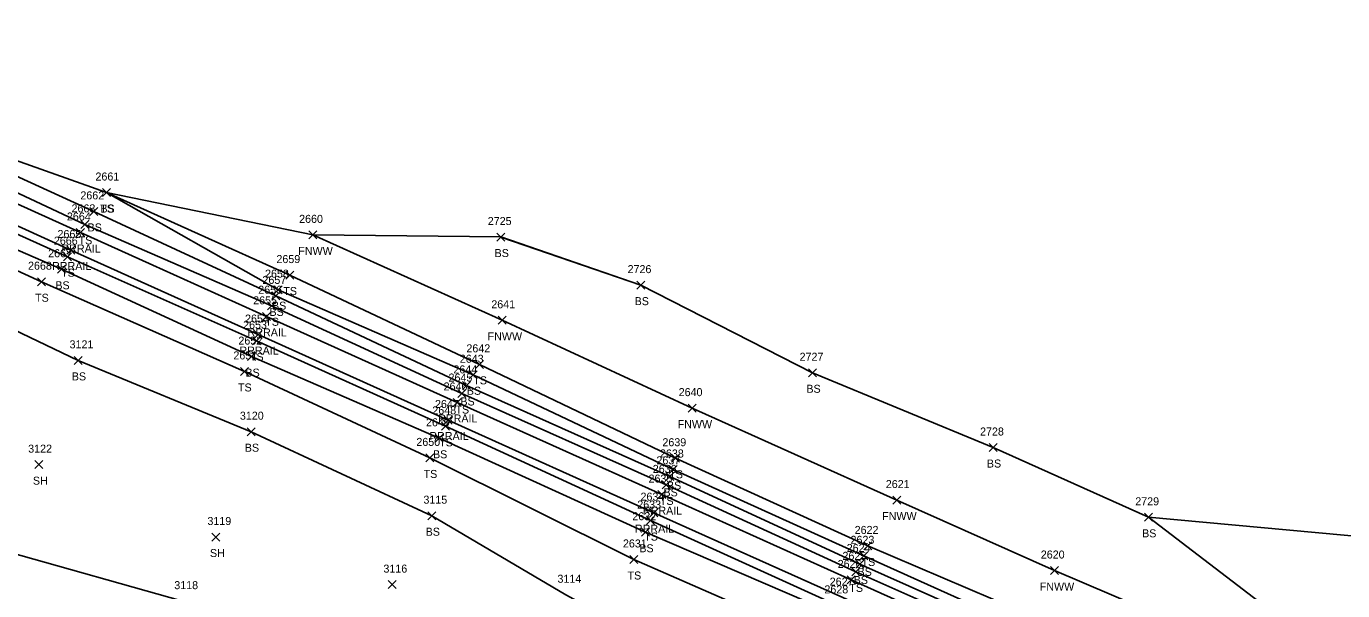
# Model space of a CAD drawing. Extents: x 1599569 to 1610055, y 642560 to 647860.
# Drawn here: x 1600804.5 to 1601133.3, y 647397.5 to 647538.4 of the extents above; entities that cross this region are included whole.
import ezdxf

# ---------------------------------------------------------------- set-up
doc = ezdxf.new("R2010")
doc.units = 0
for name, color, linetype in [('L_A', 7, 'Continuous'), ('L_I', 7, 'Continuous'), ('L_TIC', 7, 'Continuous'), ('LABL', 7, 'Continuous'), ('LELB', 7, 'Continuous'), ('LFNC', 7, 'Continuous'), ('LSOGP', 7, 'Continuous'), ('R_A', 7, 'Continuous'), ('R_I', 7, 'Continuous'), ('R_TIC', 7, 'Continuous'), ('RR', 7, 'Continuous')]:
    doc.layers.add(name, color=color, linetype=linetype)

msp = doc.modelspace()

# ---------------------------------------------------------------- linework, layer by layer
at = {"layer": 'L_TIC'}
for points in [[(1600823.54, 647495.94), (1600825.54, 647497.94)], [(1600825.54, 647495.94), (1600823.54, 647497.94)], [(1600823.54, 647495.94), (1600825.54, 647497.94)], [(1600825.54, 647495.94), (1600823.54, 647497.94)], [(1600820.34, 647491.23), (1600822.34, 647493.23)], [(1600822.34, 647491.23), (1600820.34, 647493.23)], [(1600818.14, 647487.99), (1600820.14, 647489.99)], [(1600820.14, 647487.99), (1600818.14, 647489.99)], [(1600875.08, 647485.37), (1600877.08, 647487.37)], [(1600877.08, 647485.37), (1600875.08, 647487.37)], [(1600922.02, 647484.83), (1600924.02, 647486.83)], [(1600924.02, 647484.83), (1600922.02, 647486.83)], [(1600813.78, 647479.92), (1600815.78, 647481.92)], [(1600815.78, 647479.92), (1600813.78, 647481.92)], [(1600812.3, 647476.78), (1600814.3, 647478.78)], [(1600814.3, 647476.78), (1600812.3, 647478.78)], [(1600869.28, 647475.33), (1600871.28, 647477.33)], [(1600871.28, 647475.33), (1600869.28, 647477.33)], [(1600807.26, 647473.67), (1600809.26, 647475.67)], [(1600809.26, 647473.67), (1600807.26, 647475.67)], [(1600866.43, 647471.68), (1600868.43, 647473.68)], [(1600868.43, 647471.68), (1600866.43, 647473.68)], [(1600957.02, 647472.82), (1600959.02, 647474.82)], [(1600959.02, 647472.82), (1600957.02, 647474.82)], [(1600864.78, 647467.67), (1600866.78, 647469.67)], [(1600866.78, 647467.67), (1600864.78, 647469.67)], [(1600865.79, 647470.13), (1600867.79, 647472.13)], [(1600867.79, 647470.13), (1600865.79, 647472.13)], [(1600922.39, 647464.04), (1600924.39, 647466.04)], [(1600924.39, 647464.04), (1600922.39, 647466.04)], [(1600860.95, 647458.92), (1600862.95, 647460.92)], [(1600862.95, 647458.92), (1600860.95, 647460.92)], [(1600859.78, 647454.97), (1600861.78, 647456.97)], [(1600861.78, 647454.97), (1600859.78, 647456.97)], [(1600816.41, 647454.03), (1600818.41, 647456.03)], [(1600818.41, 647454.03), (1600816.41, 647456.03)], [(1600857.96, 647451.27), (1600859.96, 647453.27)], [(1600859.96, 647451.27), (1600857.96, 647453.27)], [(1600916.74, 647453.04), (1600918.74, 647455.04)], [(1600918.74, 647453.04), (1600916.74, 647455.04)], [(1600999.93, 647450.94), (1601001.93, 647452.94)], [(1601001.93, 647450.94), (1600999.93, 647452.94)], [(1600913.49, 647447.77), (1600915.49, 647449.77)], [(1600915.49, 647447.77), (1600913.49, 647449.77)], [(1600915.08, 647450.44), (1600917.08, 647452.44)], [(1600917.08, 647450.44), (1600915.08, 647452.44)], [(1600912.28, 647445.74), (1600914.28, 647447.74)], [(1600914.28, 647445.74), (1600912.28, 647447.74)], [(1600969.86, 647442.1), (1600971.86, 647444.1)], [(1600971.86, 647442.1), (1600969.86, 647444.1)], [(1600859.62, 647436.22), (1600861.62, 647438.22)], [(1600861.62, 647436.22), (1600859.62, 647438.22)], [(1600906.65, 647434.58), (1600908.65, 647436.58)], [(1600908.65, 647434.58), (1600906.65, 647436.58)], [(1600908.23, 647437.57), (1600910.23, 647439.57)], [(1600910.23, 647437.57), (1600908.23, 647439.57)], [(1601045.02, 647432.27), (1601047.02, 647434.27)], [(1601047.02, 647432.27), (1601045.02, 647434.27)], [(1600806.64, 647427.99), (1600808.64, 647429.99)], [(1600808.64, 647427.99), (1600806.64, 647429.99)], [(1600904.33, 647429.67), (1600906.33, 647431.67)], [(1600906.33, 647429.67), (1600904.33, 647431.67)], [(1600965.71, 647429.59), (1600967.71, 647431.59)], [(1600967.71, 647429.59), (1600965.71, 647431.59)], [(1600964.22, 647425.07), (1600966.22, 647427.07)], [(1600966.22, 647425.07), (1600964.22, 647427.07)], [(1600965.1, 647426.78), (1600967.1, 647428.78)], [(1600967.1, 647426.78), (1600965.1, 647428.78)], [(1600963.35, 647422.93), (1600965.35, 647424.93)], [(1600965.35, 647422.93), (1600963.35, 647424.93)], [(1601020.95, 647419.15), (1601022.95, 647421.15)], [(1601022.95, 647419.15), (1601020.95, 647421.15)], [(1600904.82, 647415.24), (1600906.82, 647417.24)], [(1600906.82, 647415.24), (1600904.82, 647417.24)], [(1601083.8, 647414.84), (1601085.8, 647416.84)], [(1601085.8, 647414.84), (1601083.8, 647416.84)], [(1600959.43, 647414.03), (1600961.43, 647416.03)], [(1600961.43, 647414.03), (1600959.43, 647416.03)], [(1600850.87, 647409.92), (1600852.87, 647411.92)], [(1600852.87, 647409.92), (1600850.87, 647411.92)], [(1600958.19, 647411.11), (1600960.19, 647413.11)], [(1600960.19, 647411.11), (1600958.19, 647413.11)], [(1601012.7, 647405.22), (1601014.7, 647407.22)], [(1601014.7, 647405.22), (1601012.7, 647407.22)], [(1601013.73, 647407.69), (1601015.73, 647409.69)], [(1601015.73, 647407.69), (1601013.73, 647409.69)], [(1600955.28, 647404.31), (1600957.28, 647406.31)], [(1600957.28, 647404.31), (1600955.28, 647406.31)], [(1601011.74, 647403.18), (1601013.74, 647405.18)], [(1601013.74, 647403.18), (1601011.74, 647405.18)], [(1601060.33, 647401.55), (1601062.33, 647403.55)], [(1601062.33, 647401.55), (1601060.33, 647403.55)], [(1601010.7, 647401.22), (1601012.7, 647403.22)], [(1601012.7, 647401.22), (1601010.7, 647403.22)], [(1600894.88, 647398.03), (1600896.88, 647400.03)], [(1600896.88, 647398.03), (1600894.88, 647400.03)]]:
    msp.add_lwpolyline(points, dxfattribs=at)
at = {"layer": 'LABL'}
msp.add_lwpolyline([(1600549.16, 647482.12), (1600587.34, 647468), (1600622.01, 647455.54), (1600659.72, 647441.77), (1600697.35, 647428.92), (1600725.07, 647418.09), (1600758.35, 647406.43), (1600789.53, 647394.65), (1600829.98, 647379.88), (1600858.93, 647365.17), (1600893.05, 647356.35), (1600928.59, 647369.58), (1600886.67, 647382.78), (1600843.57, 647394.9), (1600799.84, 647407.24), (1600758.94, 647419.51), (1600717.33, 647433.23), (1600675.44, 647448.96), (1600633.1, 647463.38), (1600594.68, 647476.25), (1600537.7, 647496.6)], dxfattribs=at)
at = {"layer": 'LELB'}
for points in [[(1601042.57, 647341.43), (1601046.92, 647357.23), (1601002.18, 647385.23), (1600956.28, 647405.31), (1600905.33, 647430.67), (1600858.96, 647452.27), (1600808.26, 647474.67), (1600756.41, 647498.48), (1600709.6, 647519.51), (1600666.09, 647538.44)], [(1601329.86, 647260.18), (1601292.61, 647278.06), (1601262.72, 647292.4), (1601226.59, 647308.21), (1601190.68, 647323.36), (1601158.75, 647338.43), (1601129.91, 647351.62), (1601096.68, 647366.43), (1601056.58, 647384.54), (1601012.74, 647404.18), (1600965.22, 647426.07), (1600914.49, 647448.77), (1600866.79, 647471.13), (1600821.34, 647492.23), (1600763.72, 647518.52)], [(1601329.08, 647258.95), (1601292.39, 647275.61), (1601261.46, 647289.71), (1601225.27, 647305.87), (1601190.14, 647321.67), (1601157.62, 647336.35), (1601128.98, 647349.36), (1601095.53, 647364.39), (1601055.96, 647382.57), (1601011.7, 647402.22), (1600964.35, 647423.93), (1600913.28, 647446.74), (1600865.78, 647468.67), (1600819.14, 647488.99), (1600762.95, 647515.26)], [(1601006.37, 647351.71), (1601004.39, 647364.75), (1600971.27, 647379.2), (1600939.3, 647396.5), (1600905.82, 647416.24), (1600860.62, 647437.22), (1600817.41, 647455.03), (1600778.97, 647473.37), (1600739.63, 647487.55), (1600693.85, 647507.84)], [(1601326.17, 647250.65), (1601291.06, 647266.1), (1601257.88, 647281.25), (1601220.45, 647296.99), (1601187.26, 647312.94), (1601153.32, 647328.3), (1601124.87, 647340.95), (1601091.41, 647355.79), (1601053.43, 647373.03), (1601007.18, 647393.84), (1600960.43, 647415.03), (1600909.23, 647438.57), (1600861.95, 647459.92), (1600814.78, 647480.92), (1600758.97, 647506.06)], [(1601324.87, 647247.72), (1601290.33, 647262.4), (1601257.07, 647278.05), (1601219.4, 647295.14), (1601185.88, 647311.18), (1601152.37, 647326.07), (1601123.71, 647338.45), (1601090.36, 647353.63), (1601052.5, 647371.13), (1601006, 647391.96), (1600959.19, 647412.11), (1600907.65, 647435.58), (1600860.78, 647455.97), (1600813.3, 647477.78), (1600757.71, 647501.96)], [(1601277.64, 647306.94), (1601247.91, 647313.96), (1601233.47, 647321.04), (1601196.65, 647335.07), (1601162.36, 647345.97), (1601131.17, 647354.49), (1601097.9, 647368.75), (1601057.17, 647386.63), (1601013.7, 647406.22), (1600966.1, 647427.78), (1600916.08, 647451.44), (1600867.43, 647472.68), (1600824.54, 647496.94)], [(1601163.89, 647358.89), (1601162.92, 647352.78), (1601136.88, 647363.46), (1601101.2, 647375.84), (1601058.43, 647390.08), (1601014.73, 647408.69), (1600966.71, 647430.59), (1600917.74, 647454.04), (1600870.28, 647476.33), (1600824.54, 647496.94)], [(1600923.02, 647485.83), (1600958.02, 647473.82), (1601000.93, 647451.94), (1601046.02, 647433.27), (1601084.8, 647415.84), (1601116.74, 647391.45), (1601157.19, 647373.2)]]:
    msp.add_lwpolyline(points, dxfattribs=at)
at = {"layer": 'LFNC'}
msp.add_lwpolyline([(1601438.38, 647230.38), (1601406.08, 647246.23), (1601390.36, 647253.65), (1601325.07, 647284.52), (1601295.93, 647298.24), (1601277.64, 647306.94), (1601251.54, 647319.32), (1601236.24, 647326.06), (1601200.38, 647343.03), (1601163.89, 647358.89), (1601138.18, 647369.81), (1601105.25, 647383.87), (1601061.33, 647402.55), (1601021.95, 647420.15), (1600970.86, 647443.1), (1600923.39, 647465.04), (1600876.08, 647486.37)], dxfattribs=at)
at = {"layer": 'LSOGP'}
msp.add_lwpolyline([(1601329.63, 647421.95), (1601289.24, 647420.17), (1601272.46, 647419.67), (1601258.21, 647415.18), (1601255.18, 647413.85), (1601254.97, 647413.31), (1601235.02, 647405.14), (1601227.44, 647408.51), (1601219.86, 647411.89), (1601212.28, 647415.27), (1601190.18, 647411.64), (1601176.24, 647407.45), (1601084.8, 647415.84), (1601084.8, 647415.85), (1601046.02, 647433.27), (1601000.93, 647451.95), (1600958.02, 647473.82), (1600923.02, 647485.84), (1600876.08, 647486.37), (1600824.54, 647496.94), (1600763.73, 647518.52)], dxfattribs=at)
at = {"layer": 'R_TIC'}
for points in [[(1600816.98, 647485.96), (1600818.98, 647487.96)], [(1600818.98, 647485.96), (1600816.98, 647487.96)], [(1600814.63, 647481.59), (1600816.63, 647483.59)], [(1600816.63, 647481.59), (1600814.63, 647483.59)], [(1600863.46, 647465.02), (1600865.46, 647467.02)], [(1600865.46, 647465.02), (1600863.46, 647467.02)], [(1600861.44, 647460.47), (1600863.44, 647462.47)], [(1600863.44, 647460.47), (1600861.44, 647462.47)], [(1600911.09, 647443.53), (1600913.09, 647445.53)], [(1600913.09, 647443.53), (1600911.09, 647445.53)], [(1600908.88, 647439.14), (1600910.88, 647441.14)], [(1600910.88, 647439.14), (1600908.88, 647441.14)], [(1600962.24, 647420.51), (1600964.24, 647422.51)], [(1600964.24, 647420.51), (1600962.24, 647422.51)], [(1600960.24, 647416), (1600962.24, 647418)], [(1600962.24, 647416), (1600960.24, 647418)], [(1601009.55, 647399.2), (1601011.55, 647401.2)], [(1601011.55, 647399.2), (1601009.55, 647401.2)]]:
    msp.add_lwpolyline(points, dxfattribs=at)
at = {"layer": 'RR'}
for points in [[(1601328.26, 647256.93), (1601292.48, 647273.14), (1601260.65, 647287.58), (1601223.96, 647303.96), (1601189.34, 647319.67), (1601156.57, 647334.47), (1601128.05, 647347.29), (1601094.57, 647362.49), (1601054.86, 647380.37), (1601010.55, 647400.2), (1600963.24, 647421.51), (1600912.09, 647444.53), (1600864.46, 647466.02), (1600817.98, 647486.96), (1600761.67, 647512.45)], [(1601326.5, 647252.29), (1601291.28, 647268.22), (1601258.56, 647283.04), (1601221.6, 647299.6), (1601187.65, 647314.96), (1601154.54, 647329.95), (1601125.78, 647342.91), (1601092.45, 647357.88), (1601054.06, 647375.24), (1601008.5, 647395.78), (1600961.24, 647417), (1600909.88, 647440.14), (1600862.44, 647461.47), (1600815.63, 647482.59), (1600759.94, 647507.87)]]:
    msp.add_lwpolyline(points, dxfattribs=at)

# ---------------------------------------------------------------- texts
at = {"layer": 'L_A'}
for s, p in [('TS', (1600822.95, 647491.94)), ('BS', (1600822.99, 647491.94)), ('BS', (1600819.78, 647487.23)), ('TS', (1600817.54, 647483.99)), ('FNWW', (1600872.43, 647481.37)), ('BS', (1600921.47, 647480.83)), ('TS', (1600813.19, 647475.92)), ('BS', (1600811.74, 647472.78)), ('TS', (1600868.69, 647471.33)), ('TS', (1600806.67, 647469.67)), ('BS', (1600865.87, 647467.68)), ('BS', (1600956.46, 647468.82)), ('BS', (1600865.23, 647466.13)), ('TS', (1600864.19, 647463.67)), ('FNWW', (1600919.73, 647460.04)), ('TS', (1600860.36, 647454.92)), ('BS', (1600859.22, 647450.97)), ('BS', (1600815.85, 647450.03)), ('TS', (1600916.15, 647449.04)), ('TS', (1600857.37, 647447.27)), ('BS', (1600914.53, 647446.44)), ('BS', (1600999.37, 647446.94)), ('TS', (1600911.69, 647441.74)), ('BS', (1600912.93, 647443.77)), ('FNWW', (1600967.2, 647438.1)), ('BS', (1600859.07, 647432.22)), ('TS', (1600907.64, 647433.57)), ('BS', (1600906.09, 647430.58)), ('BS', (1601044.46, 647428.27)), ('TS', (1600903.74, 647425.67)), ('TS', (1600965.12, 647425.59)), ('SH', (1600806.13, 647423.99)), ('BS', (1600964.54, 647422.78)), ('TS', (1600962.76, 647418.93)), ('BS', (1600963.66, 647421.07)), ('FNWW', (1601018.3, 647415.15)), ('BS', (1600904.26, 647411.24)), ('TS', (1600958.84, 647410.03)), ('BS', (1601083.24, 647410.84)), ('SH', (1600850.36, 647405.92)), ('BS', (1600957.63, 647407.11)), ('TS', (1601013.14, 647403.69)), ('TS', (1600954.69, 647400.31)), ('BS', (1601011.18, 647399.18)), ('BS', (1601012.15, 647401.22)), ('TS', (1601010.1, 647397.22)), ('FNWW', (1601057.67, 647397.55))]:
    msp.add_text(s, height=2, dxfattribs=at).set_placement(p)
at = {"layer": 'L_I'}
for s, p in [('2661', (1600821.76, 647499.94)), ('2661', (1600821.76, 647499.94)), ('2662', (1600817.99, 647495.23)), ('2663', (1600815.78, 647491.99)), ('2660', (1600872.64, 647489.37)), ('2725', (1600919.77, 647488.83)), ('2666', (1600811.37, 647483.92)), ('2667', (1600809.94, 647480.78)), ('2668', (1600804.91, 647477.67)), ('2659', (1600866.97, 647479.33)), ('2657', (1600863.48, 647474.13)), ('2658', (1600864.12, 647475.68)), ('2726', (1600954.7, 647476.82)), ('2656', (1600862.42, 647471.67)), ('2641', (1600920.65, 647468.04)), ('2653', (1600858.65, 647462.92)), ('3121', (1600815.29, 647458.03)), ('2652', (1600857.47, 647458.97)), ('2651', (1600856.22, 647455.27)), ('2643', (1600912.78, 647454.44)), ('2642', (1600914.43, 647457.04)), ('2727', (1600997.67, 647454.94)), ('2644', (1600911.18, 647451.77)), ('2645', (1600909.97, 647449.74)), ('2640', (1600967.46, 647446.1)), ('2648', (1600905.92, 647441.57)), ('3120', (1600857.84, 647440.22)), ('2649', (1600904.33, 647438.58)), ('2728', (1601042.76, 647436.27)), ('3122', (1600804.95, 647431.99)), ('2650', (1600901.93, 647433.67)), ('2639', (1600963.4, 647433.59)), ('2637', (1600961.91, 647429.07)), ('2638', (1600962.79, 647430.78)), ('2636', (1600960.99, 647426.93)), ('2621', (1601019.21, 647423.15)), ('3115', (1600903.69, 647419.24)), ('2633', (1600957.12, 647418.03)), ('2729', (1601081.53, 647418.84)), ('2632', (1600955.88, 647415.11)), ('3119', (1600849.73, 647413.92)), ('2622', (1601011.43, 647411.69)), ('2631', (1600953.54, 647408.31)), ('2623', (1601010.4, 647409.22)), ('2625', (1601008.39, 647405.22)), ('2624', (1601009.44, 647407.18)), ('2620', (1601057.93, 647405.55)), ('3116', (1600893.7, 647402.03)), ('3114', (1600937.18, 647399.5)), ('3118', (1600841.45, 647397.9)), ('2628', (1601003.87, 647396.84))]:
    msp.add_text(s, height=2, dxfattribs=at).set_placement(p)
at = {"layer": 'R_A'}
for p in [(1600813.27, 647481.96), (1600810.92, 647477.59), (1600859.76, 647461.02), (1600857.73, 647456.47), (1600907.38, 647439.53), (1600905.17, 647435.14), (1600958.53, 647416.51), (1600956.53, 647412)]:
    msp.add_text('RRRAIL', height=2, dxfattribs=at).set_placement(p)
at = {"layer": 'R_I'}
for s, p in [('2664', (1600814.63, 647489.96)), ('2665', (1600812.28, 647485.59)), ('2655', (1600861.16, 647469.02)), ('2654', (1600859.13, 647464.47)), ('2646', (1600908.73, 647447.53)), ('2647', (1600906.58, 647443.14)), ('2635', (1600959.93, 647424.51)), ('2634', (1600957.93, 647420)), ('2626', (1601007.19, 647403.2)), ('2627', (1601005.19, 647398.78))]:
    msp.add_text(s, height=2, dxfattribs=at).set_placement(p)

doc.saveas('drawing.dxf')
